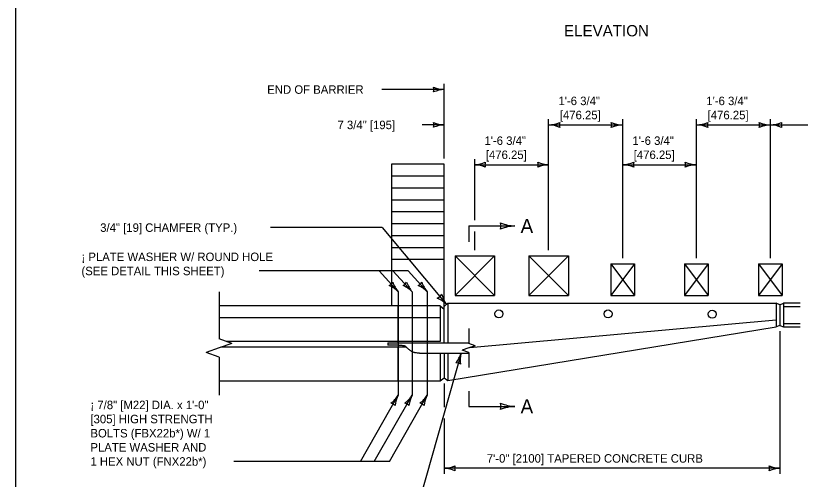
# Model space of a CAD drawing. Extents: x 49991.4 to 50021, y 49987.6 to 50011.4.
# Drawn here: x 49999.38 to 50004.93, y 49992.49 to 49995.77 of the extents above; entities that cross this region are included whole.
import ezdxf

# ---------------------------------------------------------------- set-up
doc = ezdxf.new("R2010")
doc.units = 0
for name, color, linetype in [('Level 1', 7, 'Continuous'), ('Level 2', 7, 'Continuous'), ('Level 3', 7, 'Continuous'), ('Level 5', 7, 'Continuous'), ('Level 6', 7, 'Continuous')]:
    doc.layers.add(name, color=color, linetype=linetype)

msp = doc.modelspace()

# ---------------------------------------------------------------- linework, layer by layer
at = {"layer": 'Level 1'}
for p, q in [((50002.415, 49994.7232), (50002.0423, 49994.7232)), ((50002.0423, 49994.7232), (50002.0423, 49993.721)), ((50002.415, 49993.4614), (50002.415, 49994.7232)), ((50002.415, 49994.6395), (50002.0423, 49994.6395)), ((50002.415, 49994.5547), (50002.0423, 49994.5547)), ((50002.415, 49994.4701), (50002.0423, 49994.4701)), ((50002.415, 49994.387), (50002.0423, 49994.387)), ((50002.415, 49994.3013), (50002.0423, 49994.3013)), ((50002.415, 49994.2172), (50002.0423, 49994.2172)), ((50002.415, 49994.1328), (50002.0423, 49994.1328)), ((50002.415, 49994.0492), (50002.0423, 49994.0492)), ((50002.4916, 49994.075), (50002.4916, 49993.7961)), ((50002.4916, 49994.075), (50002.7705, 49994.075)), ((50002.4916, 49994.075), (50002.7705, 49993.7961)), ((50002.7705, 49994.075), (50002.4916, 49993.7961)), ((50002.7705, 49994.075), (50002.7705, 49993.7961)), ((50003.0145, 49994.075), (50003.0145, 49993.7961)), ((50003.0145, 49994.075), (50003.2933, 49994.075)), ((50003.0145, 49994.075), (50003.2933, 49993.7961)), ((50003.2933, 49994.075), (50003.0145, 49993.7961)), ((50003.2933, 49994.075), (50003.2933, 49993.7961)), ((50003.593, 49994.0192), (50003.593, 49993.7961)), ((50003.593, 49994.0192), (50003.7603, 49994.0192)), ((50003.7603, 49994.0192), (50003.593, 49993.7961)), ((50003.593, 49994.0192), (50003.7603, 49993.7961)), ((50003.7603, 49994.0192), (50003.7603, 49993.7961)), ((50004.1159, 49994.0192), (50004.1159, 49993.7961)), ((50004.1159, 49994.0192), (50004.2832, 49994.0192)), ((50004.2832, 49994.0192), (50004.1159, 49993.7961)), ((50004.1159, 49994.0192), (50004.2832, 49993.7961)), ((50004.2832, 49994.0192), (50004.2832, 49993.7961)), ((50004.6388, 49994.0192), (50004.6388, 49993.7961)), ((50004.6388, 49994.0192), (50004.8061, 49994.0192)), ((50004.8061, 49994.0192), (50004.6388, 49993.7961)), ((50004.6388, 49994.0192), (50004.8061, 49993.7961)), ((50004.8061, 49994.0192), (50004.8061, 49993.7961)), ((50002.4916, 49993.7961), (50002.7705, 49993.7961)), ((50003.0145, 49993.7961), (50003.2933, 49993.7961)), ((50003.593, 49993.7961), (50003.7603, 49993.7961)), ((50004.1159, 49993.7961), (50004.2832, 49993.7961)), ((50004.6388, 49993.7961), (50004.8061, 49993.7961)), ((50002.3867, 49993.721), (50000.822, 49993.721)), ((50002.0873, 49993.721), (50002.0873, 49993.4614)), ((50002.3867, 49993.721), (50002.415, 49993.698)), ((50002.3867, 49993.721), (50002.3867, 49993.47)), ((50002.415, 49993.7174), (50002.4404, 49993.7403)), ((50002.4404, 49993.7403), (50004.7643, 49993.7403)), ((50002.4404, 49993.7403), (50002.4404, 49993.4614)), ((50004.7643, 49993.7403), (50004.7643, 49993.5723)), ((50004.7892, 49993.7286), (50004.7643, 49993.7403)), ((50004.7892, 49993.7286), (50004.814, 49993.7403)), ((50004.7892, 49993.7286), (50004.7892, 49993.5818)), ((50004.814, 49993.7403), (50004.814, 49993.573)), ((50004.934, 49993.7403), (50004.814, 49993.7403)), ((50004.814, 49993.7181), (50004.934, 49993.7181)), ((50002.3867, 49993.6373), (50000.822, 49993.6373)), ((50002.595, 49993.4264), (50004.7643, 49993.6229)), ((50004.814, 49993.597), (50004.934, 49993.597)), ((50002.4404, 49993.1936), (50004.7643, 49993.5723)), ((50004.7892, 49993.5818), (50004.7643, 49993.5723)), ((50004.7892, 49993.5818), (50004.814, 49993.573)), ((50004.814, 49993.573), (50004.934, 49993.573)), ((50002.1487, 49993.4285), (50000.8344, 49993.4285)), ((50002.3867, 49993.47), (50000.8753, 49993.47)), ((50002.0158, 49993.4614), (50002.5882, 49993.4614)), ((50002.0158, 49993.4614), (50002.0158, 49993.4427)), ((50002.0902, 49993.4427), (50002.0158, 49993.4427)), ((50002.0873, 49993.4285), (50002.0873, 49993.1911)), ((50002.2399, 49993.3866), (50002.5882, 49993.3866)), ((50002.3867, 49993.3866), (50002.3867, 49993.1911)), ((50002.4149, 49993.3866), (50002.4149, 49993.2129)), ((50002.4403, 49993.3866), (50002.4403, 49993.1936)), ((50000.822, 49993.1911), (50002.3867, 49993.1911))]:
    msp.add_line(p, q, dxfattribs=at)
msp.add_lwpolyline([(49999.3835, 49998.9992), (50016.7501, 49998.9992), (50016.7501, 49987.7988), (49999.3835, 49987.7988)], close=True, dxfattribs=at)
msp.add_lwpolyline([(50002.3867, 49993.1911), (50002.4149, 49993.2129), (50002.4403, 49993.1936)], dxfattribs=at)
for centre in [(50002.8014, 49993.6653), (50003.5739, 49993.6653), (50004.3108, 49993.663)]:
    msp.add_circle(centre, 0.0283, dxfattribs=at)
msp.add_spline([(50002.2399, 49993.3866), (50002.2106, 49993.3899), (50002.2069, 49993.3904), (50002.2032, 49993.3912), (50002.1959, 49993.3935), (50002.1889, 49993.3966), (50002.1855, 49993.3985), (50002.1822, 49993.4005), (50002.1751, 49993.4053), (50002.1683, 49993.4104), (50002.1619, 49993.4158), (50002.1557, 49993.4216), (50002.1468, 49993.4304), (50002.1433, 49993.4339), (50002.1395, 49993.4364), (50002.1351, 49993.4379), (50002.1256, 49993.4392), (50002.1168, 49993.4404), (50002.1079, 49993.4415), (50002.0991, 49993.4424), (50002.0902, 49993.4427)], degree=3, dxfattribs=at)
at = {"layer": 'Level 3'}
for p, q in [((50002.415, 49995.2518), (50001.9729, 49995.2518)), ((50002.415, 49994.7632), (50002.415, 49995.2918)), ((50003.1538, 49994.115), (50003.1538, 49995.0417)), ((50003.6767, 49995.0417), (50003.6767, 49994.0592)), ((50004.1995, 49994.0592), (50004.1995, 49995.0417)), ((50004.7224, 49994.0592), (50004.7224, 49995.0417)), ((50002.415, 49995.0018), (50002.2582, 49995.0018)), ((50003.1539, 49995.0017), (50003.6767, 49995.0017)), ((50004.1997, 49995.0017), (50004.7225, 49995.0017)), ((50004.7225, 49995.0017), (50005.7683, 49995.0017)), ((50002.6297, 49994.7604), (50002.6297, 49994.3268)), ((50002.6297, 49994.7204), (50003.1538, 49994.7204)), ((50003.6768, 49994.7204), (50004.1995, 49994.7204)), ((50001.9762, 49994.2752), (50001.186, 49994.2752)), ((50001.9762, 49994.2752), (50002.4309, 49993.7317)), ((50002.6296, 49994.2468), (50002.6296, 49994.115)), ((50002.1595, 49993.9686), (50001.1066, 49993.9686)), ((50001.9544, 49993.9686), (50002.0902, 49993.821)), ((50002.0526, 49993.9686), (50002.1884, 49993.821)), ((50002.1595, 49993.9686), (50002.2953, 49993.821)), ((50004.7892, 49993.5418), (50004.7892, 49993.4276)), ((50004.7892, 49993.4262), (50004.7892, 49992.5326)), ((50002.5343, 49993.3866), (50002.2339, 49992.3241)), ((50002.4149, 49993.1728), (50002.4149, 49993.0044)), ((50001.8223, 49992.6211), (50002.0902, 49993.0911)), ((50001.9204, 49992.6211), (50002.1884, 49993.0911)), ((50002.0274, 49992.6211), (50002.2953, 49993.0911)), ((50002.4149, 49992.9244), (50002.4149, 49992.5326)), ((50002.0274, 49992.6211), (50000.9257, 49992.6211)), ((50004.7892, 49992.5726), (50002.4149, 49992.5726))]:
    msp.add_line(p, q, dxfattribs=at)
for centre, radius, start, end in [((50002.4242, 49995.4739), 0.2223, 247.456, 267.6395), ((50002.2868, 49995.2518), 0.0548, 342.1388, 17.8612), ((50002.4265, 49995.0191), 0.233, 92.8273, 112.0772), ((50002.4242, 49995.2239), 0.2223, 247.456, 267.6395), ((50002.2868, 49995.0018), 0.0548, 342.1388, 17.8612), ((50002.4265, 49994.7691), 0.233, 92.8273, 112.0772), ((50003.1418, 49995.2451), 0.2437, 272.8273, 292.0772), ((50003.1442, 49994.7694), 0.2325, 67.456, 87.6395), ((50003.2879, 49995.0017), 0.0573, 162.1388, 197.8612), ((50003.6862, 49995.234), 0.2325, 247.456, 267.6395), ((50003.5426, 49995.0017), 0.0573, 342.1388, 17.8612), ((50003.6887, 49994.7584), 0.2437, 92.8273, 112.0772), ((50004.1875, 49995.2451), 0.2437, 272.8273, 292.0772), ((50004.19, 49994.7694), 0.2325, 67.456, 87.6395), ((50004.3336, 49995.0017), 0.0573, 162.1388, 197.8612), ((50004.732, 49995.234), 0.2325, 247.456, 267.6395), ((50004.5883, 49995.0017), 0.0573, 342.1388, 17.8612), ((50004.7344, 49994.7584), 0.2437, 92.8273, 112.0772), ((50004.7104, 49995.2451), 0.2437, 272.8273, 292.0772), ((50004.7128, 49994.7694), 0.2325, 67.456, 87.6395), ((50004.8565, 49995.0017), 0.0573, 162.1388, 197.8612), ((50002.6182, 49994.9531), 0.233, 272.8273, 292.0772), ((50002.6205, 49994.4983), 0.2223, 67.456, 87.6395), ((50002.7579, 49994.7204), 0.0548, 162.1388, 197.8612), ((50003.1629, 49994.9425), 0.2223, 247.456, 267.6395), ((50003.0256, 49994.7204), 0.0548, 342.1388, 17.8612), ((50003.1653, 49994.4877), 0.233, 92.8273, 112.0772), ((50003.6646, 49994.9638), 0.2437, 272.8273, 292.0772), ((50003.6671, 49994.4881), 0.2325, 67.456, 87.6395), ((50003.8107, 49994.7204), 0.0573, 162.1388, 197.8612), ((50004.2091, 49994.9527), 0.2325, 247.456, 267.6395), ((50004.0655, 49994.7204), 0.0573, 342.1388, 17.8612), ((50004.2116, 49994.4771), 0.2437, 92.8273, 112.0772), ((50002.9274, 49994.583), 0.2964, 247.456, 267.6395), ((50002.7443, 49994.2868), 0.073, 342.1388, 17.8612), ((50002.9305, 49993.9765), 0.3106, 92.8273, 112.0772), ((50002.0034, 49993.9154), 0.0548, 294.7543, 330.4767), ((50001.9267, 49993.655), 0.233, 45.4428, 64.6927), ((50002.2599, 49993.9647), 0.2223, 200.0715, 220.255), ((50002.1016, 49993.9154), 0.0548, 294.7543, 330.4767), ((50002.0249, 49993.655), 0.233, 45.4428, 64.6927), ((50002.3581, 49993.9647), 0.2223, 200.0715, 220.255), ((50002.2085, 49993.9154), 0.0548, 294.7578, 330.4802), ((50002.1318, 49993.655), 0.233, 45.4463, 64.6961), ((50002.465, 49993.9647), 0.2223, 200.075, 220.2585), ((50002.3233, 49993.4566), 0.2223, 321.4592, 341.6427), ((50002.7611, 49993.3335), 0.233, 166.8305, 186.0804), ((50002.4989, 49993.2634), 0.0548, 56.142, 91.8644), ((50001.9018, 49993.2091), 0.2223, 307.7717, 327.9552), ((50002.2981, 49992.9858), 0.233, 153.143, 172.3929), ((50002, 49993.2091), 0.2223, 307.7649, 327.9484), ((50002.3962, 49992.9858), 0.233, 153.1362, 172.386), ((50002.1069, 49993.209), 0.2223, 307.7734, 327.957), ((50002.5032, 49992.9859), 0.233, 153.1447, 172.3946), ((50002.0267, 49992.9797), 0.0548, 42.4545, 78.1769), ((50002.1249, 49992.9797), 0.0548, 42.4477, 78.1701), ((50002.2318, 49992.9797), 0.0548, 42.4563, 78.1786), ((50002.9274, 49993.3071), 0.2964, 247.456, 267.6395), ((50002.7443, 49993.0109), 0.073, 342.1388, 17.8612), ((50002.9305, 49992.7006), 0.3106, 92.8273, 112.0772), ((50002.4034, 49992.8053), 0.233, 272.8273, 292.0772), ((50002.5431, 49992.5726), 0.0548, 162.1388, 197.8612), ((50004.7984, 49992.7947), 0.2223, 247.456, 267.6395), ((50004.661, 49992.5726), 0.0548, 342.1388, 17.8612), ((50002.4057, 49992.3505), 0.2223, 67.456, 87.6395), ((50004.8007, 49992.3399), 0.233, 92.8273, 112.0772)]:
    msp.add_arc(centre, radius, start, end, dxfattribs=at)
for centre, major_axis, start_param, end_param in [((50002.3493, 49993.8292), (-0.0535, -0.0448), 1.25906, 1.882533), ((50002.2108, 49993.5325), (0.2277, 0.1908), 0.049346, 0.385319), ((50002.6538, 49993.9066), (-0.2173, -0.182), 5.889718, 6.241987)]:
    msp.add_ellipse(centre, major_axis=major_axis, ratio=0.77736, start_param=start_param, end_param=end_param, dxfattribs=at)
at = {"layer": 'Level 5'}
for p, q in [((50002.0902, 49993.821), (50002.0902, 49993.0911)), ((50002.1884, 49993.821), (50002.1884, 49993.0911)), ((50002.2953, 49993.821), (50002.2953, 49993.0911))]:
    msp.add_line(p, q, dxfattribs=at)
at = {"layer": 'Level 6'}
for p, q in [((50002.5881, 49994.2868), (50002.5881, 49994.175)), ((50002.5882, 49994.2868), (50002.9152, 49994.2868)), ((50000.822, 49993.821), (50000.822, 49993.4889)), ((50002.5882, 49993.5614), (50002.5882, 49993.4564)), ((50000.9134, 49993.4565), (50000.822, 49993.4889)), ((50000.822, 49993.4241), (50000.7306, 49993.3917)), ((50000.9134, 49993.4565), (50000.822, 49993.4241)), ((50002.5882, 49993.424), (50002.5425, 49993.4078)), ((50002.6339, 49993.4402), (50002.5882, 49993.4564)), ((50002.6339, 49993.4402), (50002.5882, 49993.424)), ((50000.822, 49993.3593), (50000.7306, 49993.3917)), ((50002.5882, 49993.3916), (50002.5425, 49993.4078)), ((50002.5882, 49993.3916), (50002.5882, 49993.2866)), ((50000.822, 49993.3593), (50000.822, 49993.0911)), ((50002.5881, 49993.1177), (50002.5881, 49993.0109)), ((50002.5882, 49993.0109), (50002.9152, 49993.0109))]:
    msp.add_line(p, q, dxfattribs=at)

# ---------------------------------------------------------------- texts
at = {"layer": 'Level 2'}
for s, height, p in [('ELEVATION', 0.08, (50003.2625, 49995.6281)), ('END OF BARRIER', 0.06, (50001.1628, 49995.2218)), ('1\'-6 3/4"', 0.06, (50003.2232, 49995.1417)), ('1\'-6 3/4"', 0.06, (50004.269, 49995.1417)), ('[476.25]', 0.06, (50003.2325, 49995.0417)), ('[476.25]', 0.06, (50004.2783, 49995.0417)), ('7 3/4" [195]', 0.06, (50001.6598, 49994.9718)), ('1\'-6 3/4"', 0.06, (50002.6997, 49994.8604)), ('1\'-6 3/4"', 0.06, (50003.7461, 49994.8604)), ('[476.25]', 0.06, (50002.709, 49994.7604)), ('[476.25]', 0.06, (50003.7554, 49994.7604)), ('3/4" [19] CHAMFER (TYP.)', 0.06, (49999.9812, 49994.2452)), ('A', 0.1, (50002.9552, 49994.2368)), ('¡ PLATE WASHER W/ ROUND HOLE', 0.06, (49999.8486, 49994.0386)), ('(SEE DETAIL THIS SHEET)', 0.06, (49999.8486, 49993.9386)), ('¡ 7/8" [M22] DIA. x 1\'-0"', 0.06, (49999.9121, 49992.9911)), ('A', 0.1, (50002.9552, 49992.9609)), ('[305] HIGH STRENGTH', 0.06, (49999.9121, 49992.8911)), ('BOLTS (FBX22b*) W/ 1', 0.06, (49999.9121, 49992.7911)), ('PLATE WASHER AND', 0.06, (49999.9121, 49992.6911)), ('1 HEX NUT (FNX22b*)', 0.06, (49999.9121, 49992.5911)), ('7\'-0" [2100] TAPERED CONCRETE CURB', 0.06, (50002.7163, 49992.6126))]:
    msp.add_text(s, height=height, dxfattribs=at).set_placement(p)

doc.saveas('drawing.dxf')
